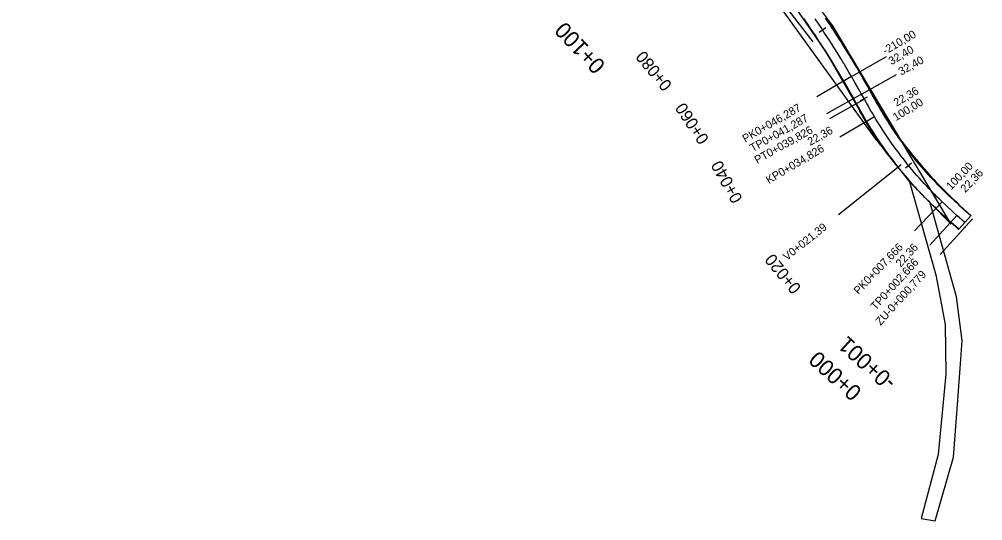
# Model space of a CAD drawing. Extents: x -636600 to -628587, y -1090963 to -1085869.
# Drawn here: x -634259.5 to -634019.5, y -1089987.9 to -1089863.1 of the extents above; entities that cross this region are included whole.
import ezdxf

# ---------------------------------------------------------------- set-up
doc = ezdxf.new("R2010")
doc.units = 0
for name, color, linetype in [('01_PARCELY_NÁVRH_PC', 7, 'Continuous'), ('06_ÚSES_IP_NAVRH', 7, 'Continuous'), ('HEKTOMETRY100', 7, 'Continuous'), ('HEKTOMETRY20', 7, 'Continuous'), ('HL_BODY', 7, 'Continuous'), ('POLOMERY', 7, 'Continuous'), ('situace_osa', 7, 'Continuous'), ('situace_těleso', 7, 'Continuous'), ('situace_vozovka', 7, 'Continuous'), ('VRCHOLY', 7, 'Continuous')]:
    doc.layers.add(name, color=color, linetype=linetype)

msp = doc.modelspace()

# ---------------------------------------------------------------- linework, layer by layer
at = {"layer": '01_PARCELY_NÁVRH_PC'}
for points in [[(-634258.18, -1089646.18), (-634176.9, -1089739.82), (-634077.43, -1089845.93), (-634067.68, -1089858), (-634058.64, -1089871.16), (-634045.93, -1089893.26), (-634037.74, -1089903.59), (-634027.4, -1089914.11), (-634040.58, -1089892.03), (-634056.88, -1089864.72), (-634067.09, -1089851.03), (-634070.76, -1089846.11), (-634158.26, -1089752.56), (-634176.72, -1089732.83), (-634240.83, -1089658.58), (-634242.34, -1089654.2), (-634241.75, -1089649.53), (-634239.18, -1089645.67)], [(-634259.52, -1089649.22), (-634255.64, -1089649.11), (-634176.9, -1089739.82), (-634077.43, -1089845.93), (-634067.68, -1089858), (-634058.64, -1089871.16), (-634045.93, -1089893.26), (-634070.08, -1089859.8), (-634079.7, -1089847.9), (-634179.12, -1089741.83)], [(-634037.74, -1089903.59), (-634031.25, -1089926.68), (-634028.92, -1089939.08), (-634028.76, -1089951.44), (-634030.67, -1089971.48), (-634034.83, -1089987.38), (-634031.35, -1089987.93), (-634026.79, -1089972.12), (-634025.98, -1089961.25), (-634025.06, -1089948.91), (-634024.63, -1089943.06), (-634026.06, -1089932.21), (-634032.66, -1089908.76)]]:
    msp.add_lwpolyline(points, close=True, dxfattribs=at)
at = {"layer": '06_ÚSES_IP_NAVRH'}
msp.add_lwpolyline([(-634061.77, -1089868.68), (-634079.73, -1089845.5), (-634182.6, -1089735.66), (-634254.9, -1089652.07)], dxfattribs=at)
at = {"layer": 'HEKTOMETRY100'}
for points in [[(-634025.35, -1089915.19), (-634022.66, -1089912.22)], [(-634024.77, -1089915.71), (-634022.08, -1089912.75)]]:
    msp.add_lwpolyline(points, dxfattribs=at)
at = {"layer": 'HEKTOMETRY20'}
for points in [[(-634060.26, -1089866.3), (-634058.6, -1089865.18)], [(-634049.96, -1089883.34), (-634048.22, -1089882.36)], [(-634038.8, -1089900.11), (-634037.25, -1089898.84)], [(-634024.1, -1089914.97), (-634022.75, -1089913.49)]]:
    msp.add_lwpolyline(points, dxfattribs=at)
at = {"layer": 'HL_BODY'}
for points in [[(-634052.19, -1089877.38), (-634060.85, -1089882.38)], [(-634049.72, -1089881.73), (-634058.44, -1089886.63)], [(-634049.01, -1089883.01), (-634057.72, -1089887.9)], [(-634046.52, -1089887.34), (-634055.11, -1089892.46)], [(-634029.65, -1089908.52), (-634036.55, -1089915.75)], [(-634025.98, -1089911.91), (-634032.7, -1089919.32)], [(-634023.42, -1089914.23), (-634030.15, -1089921.63)]]:
    msp.add_lwpolyline(points, dxfattribs=at)
at = {"layer": 'POLOMERY'}
for points in [[(-634052.19, -1089877.38), (-634043.53, -1089872.38)], [(-634049.72, -1089881.73), (-634041, -1089876.83)], [(-634049.01, -1089883.01), (-634057.72, -1089887.9)], [(-634046.52, -1089887.34), (-634055.11, -1089892.46)], [(-634029.65, -1089908.52), (-634036.55, -1089915.75)], [(-634025.98, -1089911.91), (-634032.7, -1089919.32)], [(-634023.42, -1089914.23), (-634030.15, -1089921.63)]]:
    msp.add_lwpolyline(points, dxfattribs=at)
at = {"layer": 'situace_osa'}
msp.add_lwpolyline([(-634024, -1089913.7), (-634025.98, -1089911.91), (-634026.72, -1089911.24), (-634027.45, -1089910.57), (-634027.7, -1089910.34), (-634028.19, -1089909.89), (-634028.92, -1089909.21), (-634029.65, -1089908.52), (-634030.3, -1089907.89), (-634030.95, -1089907.26), (-634031.32, -1089906.89), (-634031.59, -1089906.62), (-634032.22, -1089905.97), (-634032.85, -1089905.32), (-634033.47, -1089904.66), (-634034.09, -1089904), (-634034.7, -1089903.33), (-634034.76, -1089903.27), (-634035.31, -1089902.66), (-634035.91, -1089901.98), (-634036.5, -1089901.3), (-634037.08, -1089900.61), (-634037.66, -1089899.91), (-634038.02, -1089899.48), (-634038.24, -1089899.21), (-634038.81, -1089898.51), (-634039.37, -1089897.79), (-634039.92, -1089897.08), (-634040.47, -1089896.36), (-634041.01, -1089895.63), (-634041.09, -1089895.53), (-634041.54, -1089894.9), (-634042.07, -1089894.17), (-634042.59, -1089893.43), (-634043.11, -1089892.68), (-634043.62, -1089891.93), (-634043.95, -1089891.43), (-634044.12, -1089891.18), (-634044.61, -1089890.42), (-634045.1, -1089889.66), (-634045.58, -1089888.89), (-634046.05, -1089888.12), (-634046.52, -1089887.34), (-634046.61, -1089887.19), (-634047.03, -1089886.48), (-634047.53, -1089885.62), (-634048.02, -1089884.75), (-634048.52, -1089883.88), (-634049.01, -1089883.01), (-634049.09, -1089882.85), (-634049.72, -1089881.73), (-634050.54, -1089880.28), (-634051.36, -1089878.83), (-634051.55, -1089878.5), (-634052.19, -1089877.38), (-634052.85, -1089876.25), (-634053.51, -1089875.13), (-634054.07, -1089874.18), (-634054.18, -1089874), (-634054.86, -1089872.89), (-634055.55, -1089871.77), (-634056.24, -1089870.66), (-634056.7, -1089869.93), (-634056.94, -1089869.56), (-634057.65, -1089868.46), (-634058.36, -1089867.36), (-634059.08, -1089866.27), (-634059.43, -1089865.74), (-634059.81, -1089865.18), (-634060.54, -1089864.1), (-634061.28, -1089863.02)], dxfattribs=at)
at = {"layer": 'situace_těleso'}
msp.add_lwpolyline([(-634058.66, -1089862.81), (-634057.92, -1089863.91), (-634057.54, -1089864.48), (-634057.19, -1089865.01), (-634056.46, -1089866.11), (-634055.74, -1089867.22), (-634055.02, -1089868.34), (-634054.78, -1089868.71), (-634054.32, -1089869.45), (-634053.61, -1089870.57), (-634052.92, -1089871.7), (-634052.23, -1089872.82), (-634052.12, -1089873.01), (-634051.54, -1089873.96), (-634050.86, -1089875.09), (-634050.19, -1089876.23), (-634049.54, -1089877.35), (-634049.35, -1089877.68), (-634048.51, -1089879.14), (-634047.68, -1089880.58), (-634047.04, -1089881.7), (-634046.95, -1089881.85), (-634046.45, -1089882.71), (-634045.96, -1089883.58), (-634045.49, -1089884.45), (-634045.01, -1089885.31), (-634044.62, -1089886.01), (-634044.53, -1089886.16), (-634044.09, -1089886.93), (-634043.64, -1089887.69), (-634043.18, -1089888.45), (-634042.72, -1089889.2), (-634042.23, -1089889.93), (-634042.06, -1089890.18), (-634041.72, -1089890.66), (-634041.21, -1089891.39), (-634040.7, -1089892.1), (-634040.18, -1089892.82), (-634039.65, -1089893.53), (-634039.19, -1089894.13), (-634039.11, -1089894.23), (-634038.57, -1089894.93), (-634038.02, -1089895.62), (-634037.47, -1089896.31), (-634036.91, -1089896.99), (-634036.34, -1089897.67), (-634036.13, -1089897.93), (-634035.78, -1089898.35), (-634035.22, -1089899.03), (-634034.65, -1089899.71), (-634034.07, -1089900.38), (-634033.49, -1089901.04), (-634032.96, -1089901.64), (-634032.9, -1089901.7), (-634032.31, -1089902.36), (-634031.71, -1089903.01), (-634031.1, -1089903.65), (-634030.49, -1089904.29), (-634029.87, -1089904.92), (-634029.61, -1089905.18), (-634029.25, -1089905.55), (-634028.62, -1089906.17), (-634027.99, -1089906.78), (-634027.28, -1089907.46), (-634026.57, -1089908.13), (-634026.09, -1089908.58), (-634025.85, -1089908.81), (-634025.13, -1089909.5), (-634024.41, -1089910.18), (-634022.45, -1089912), (-634022.49, -1089912.04), (-634024, -1089913.7), (-634025.51, -1089915.37), (-634025.54, -1089915.4), (-634027.51, -1089913.6), (-634028.25, -1089912.93), (-634028.99, -1089912.25), (-634029.24, -1089912.02), (-634029.73, -1089911.56), (-634030.48, -1089910.86), (-634031.22, -1089910.16), (-634031.88, -1089909.52), (-634032.54, -1089908.87), (-634032.92, -1089908.49), (-634033.19, -1089908.21), (-634033.84, -1089907.55), (-634034.48, -1089906.88), (-634035.12, -1089906.21), (-634035.75, -1089905.53), (-634036.37, -1089904.85), (-634036.44, -1089904.78), (-634036.99, -1089904.16), (-634037.6, -1089903.46), (-634038.21, -1089902.76), (-634038.81, -1089902.06), (-634039.4, -1089901.35), (-634039.78, -1089900.91), (-634040.01, -1089900.65), (-634040.6, -1089899.94), (-634041.19, -1089899.22), (-634041.77, -1089898.5), (-634042.35, -1089897.77), (-634042.92, -1089897.04), (-634043, -1089896.93), (-634043.48, -1089896.31), (-634044.04, -1089895.56), (-634044.59, -1089894.82), (-634045.13, -1089894.06), (-634045.66, -1089893.31), (-634046.02, -1089892.8), (-634046.19, -1089892.55), (-634046.7, -1089891.77), (-634047.2, -1089890.98), (-634047.68, -1089890.19), (-634048.15, -1089889.39), (-634048.62, -1089888.59), (-634048.71, -1089888.44), (-634049.12, -1089887.7), (-634049.62, -1089886.82), (-634050.11, -1089885.93), (-634050.6, -1089885.05), (-634051.08, -1089884.17), (-634051.16, -1089884.02), (-634051.78, -1089882.89), (-634052.59, -1089881.43), (-634053.39, -1089879.98), (-634053.58, -1089879.65), (-634054.2, -1089878.55), (-634054.85, -1089877.42), (-634055.5, -1089876.31), (-634056.05, -1089875.37), (-634056.16, -1089875.19), (-634056.82, -1089874.08), (-634057.5, -1089872.98), (-634058.18, -1089871.88), (-634058.64, -1089871.16), (-634058.87, -1089870.79), (-634059.57, -1089869.7), (-634060.27, -1089868.61), (-634060.98, -1089867.53), (-634061.32, -1089867), (-634061.69, -1089866.45), (-634062.41, -1089865.38), (-634063.14, -1089864.31), (-634063.88, -1089863.24), (-634064.11, -1089862.92)], dxfattribs=at)
at = {"layer": 'situace_vozovka'}
for points in [[(-634025.51, -1089915.37), (-634027.49, -1089913.58), (-634028.23, -1089912.9), (-634028.97, -1089912.23), (-634029.22, -1089912), (-634029.72, -1089911.54), (-634030.46, -1089910.85), (-634031.2, -1089910.15), (-634031.87, -1089909.51), (-634032.53, -1089908.86), (-634032.91, -1089908.48), (-634033.18, -1089908.2), (-634033.83, -1089907.54), (-634034.48, -1089906.88), (-634035.11, -1089906.2), (-634035.74, -1089905.53), (-634036.37, -1089904.84), (-634036.43, -1089904.78), (-634036.99, -1089904.16), (-634037.6, -1089903.46), (-634038.21, -1089902.76), (-634038.81, -1089902.06), (-634039.4, -1089901.35), (-634039.76, -1089900.9), (-634039.98, -1089900.63), (-634040.56, -1089899.91), (-634041.14, -1089899.18), (-634041.71, -1089898.45), (-634042.27, -1089897.71), (-634042.82, -1089896.97), (-634042.9, -1089896.86), (-634043.37, -1089896.22), (-634043.91, -1089895.47), (-634044.44, -1089894.72), (-634044.97, -1089893.95), (-634045.49, -1089893.19), (-634045.83, -1089892.67), (-634046, -1089892.42), (-634046.5, -1089891.64), (-634047, -1089890.86), (-634047.49, -1089890.08), (-634047.98, -1089889.29), (-634048.45, -1089888.49), (-634048.55, -1089888.34), (-634048.97, -1089887.62), (-634049.48, -1089886.74), (-634049.98, -1089885.86), (-634050.48, -1089884.98), (-634050.97, -1089884.11), (-634051.05, -1089883.96), (-634051.68, -1089882.83), (-634052.5, -1089881.38), (-634053.32, -1089879.94), (-634053.5, -1089879.61), (-634054.14, -1089878.51), (-634054.79, -1089877.39), (-634055.45, -1089876.28), (-634056, -1089875.34), (-634056.11, -1089875.17), (-634056.78, -1089874.06), (-634057.46, -1089872.96), (-634058.15, -1089871.86), (-634058.6, -1089871.14), (-634058.84, -1089870.77), (-634059.54, -1089869.68), (-634060.24, -1089868.59), (-634060.95, -1089867.51), (-634061.3, -1089866.99), (-634061.67, -1089866.44), (-634062.4, -1089865.37), (-634063.13, -1089864.3), (-634063.87, -1089863.24), (-634064.1, -1089862.91)], [(-634022.49, -1089912.04), (-634024.46, -1089910.25), (-634025.2, -1089909.58), (-634025.94, -1089908.91), (-634026.18, -1089908.68), (-634026.66, -1089908.24), (-634027.38, -1089907.57), (-634028.1, -1089906.89), (-634028.73, -1089906.28), (-634029.36, -1089905.66), (-634029.73, -1089905.3), (-634029.99, -1089905.03), (-634030.61, -1089904.4), (-634031.23, -1089903.77), (-634031.83, -1089903.12), (-634032.44, -1089902.48), (-634033.03, -1089901.82), (-634033.09, -1089901.76), (-634033.63, -1089901.16), (-634034.21, -1089900.5), (-634034.79, -1089899.83), (-634035.36, -1089899.16), (-634035.93, -1089898.48), (-634036.28, -1089898.05), (-634036.49, -1089897.79), (-634037.05, -1089897.1), (-634037.59, -1089896.41), (-634038.14, -1089895.71), (-634038.67, -1089895), (-634039.2, -1089894.3), (-634039.28, -1089894.19), (-634039.72, -1089893.58), (-634040.24, -1089892.86), (-634040.75, -1089892.14), (-634041.25, -1089891.41), (-634041.75, -1089890.68), (-634042.08, -1089890.19), (-634042.24, -1089889.94), (-634042.72, -1089889.2), (-634043.2, -1089888.46), (-634043.67, -1089887.71), (-634044.13, -1089886.95), (-634044.59, -1089886.19), (-634044.67, -1089886.05), (-634045.08, -1089885.35), (-634045.58, -1089884.5), (-634046.07, -1089883.64), (-634046.56, -1089882.77), (-634047.04, -1089881.9), (-634047.13, -1089881.75), (-634047.76, -1089880.63), (-634048.58, -1089879.17), (-634049.4, -1089877.72), (-634049.59, -1089877.38), (-634050.24, -1089876.26), (-634050.91, -1089875.11), (-634051.58, -1089873.98), (-634052.15, -1089873.02), (-634052.26, -1089872.84), (-634052.94, -1089871.71), (-634053.64, -1089870.59), (-634054.34, -1089869.46), (-634054.8, -1089868.72), (-634055.04, -1089868.35), (-634055.76, -1089867.23), (-634056.48, -1089866.13), (-634057.21, -1089865.02), (-634057.56, -1089864.49), (-634057.94, -1089863.92), (-634058.68, -1089862.83)]]:
    msp.add_lwpolyline(points, dxfattribs=at)
at = {"layer": 'VRCHOLY'}
msp.add_lwpolyline([(-634039.84, -1089899.33), (-634055.48, -1089911.79)], dxfattribs=at)

# ---------------------------------------------------------------- texts
at = {"layer": 'HEKTOMETRY100'}
for s, rotation, p in [('0+100', 133.1874, (-634113.28, -1089874.36)), ('-0+001', 137.7584, (-634040.79, -1089953.02)), ('0+000', 137.7584, (-634049.4, -1089955.48))]:
    msp.add_text(s, height=4, rotation=rotation, dxfattribs=at).set_placement(p)
at = {"layer": 'HEKTOMETRY20'}
for s, rotation, p in [('0+080', 129.2129, (-634096.75, -1089879.4)), ('0+060', 123.7561, (-634087.58, -1089892.92)), ('0+040', 119.3325, (-634079.25, -1089907.78)), ('0+020', 129.2595, (-634064.59, -1089929.91))]:
    msp.add_text(s, height=3, rotation=rotation, dxfattribs=at).set_placement(p)
at = {"layer": 'HL_BODY'}
for s, rotation, p in [('PK0+046,287', 30.0146, (-634078.69, -1089893.85)), ('TP0+041,287', 29.3325, (-634076.84, -1089896.2)), ('PT0+039,826', 29.3325, (-634075.7, -1089899.15)), ('KP0+034,826', 30.7649, (-634072.8, -1089904.15)), ('PK0+007,666', 46.3261, (-634050.46, -1089931.76)), ('TP0+002,666', 47.7584, (-634046.2, -1089935.67)), ('ZU-0+000,779', 47.7584, (-634044.98, -1089939.45))]:
    msp.add_text(s, height=2, rotation=rotation, dxfattribs=at).set_placement(p)
at = {"layer": 'POLOMERY'}
for s, rotation, p in [('-210,00', 30.0146, (-634043.78, -1089871.95)), ('32,40', 30.0146, (-634042.28, -1089874.55)), ('32,40', 29.3325, (-634039.84, -1089877.13)), ('22,36', 30.7649, (-634041, -1089884.89)), ('100,00', 30.7649, (-634041.17, -1089888.48)), ('22,36', 29.3325, (-634062.48, -1089894.63)), ('100,00', 46.3261, (-634027.41, -1089905.73)), ('22,36', 46.3261, (-634023.87, -1089906.37)), ('22,36', 47.7584, (-634039.96, -1089924.96))]:
    msp.add_text(s, height=2, rotation=rotation, dxfattribs=at).set_placement(p)
at = {"layer": 'VRCHOLY'}
msp.add_text('V0+021,39', height=2, rotation=38.5455, dxfattribs=at).set_placement((-634068.32, -1089923.3))

doc.saveas('drawing.dxf')
